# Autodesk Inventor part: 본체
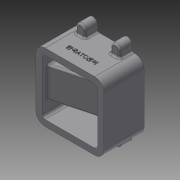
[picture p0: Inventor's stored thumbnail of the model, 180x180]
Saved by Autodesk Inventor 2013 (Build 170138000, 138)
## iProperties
Created: 2018-01
Part Number: 본체
Material: 일반
Document SubType Name: Modeling
Designer: Administrator
Density: 1 g/cm^3
Author: Administrator
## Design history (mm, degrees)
sketch "스케치1"
  geometry: L1 (55, -55)-(-55, -55); L2 (-55, -55)-(-55, 55); L3 (-55, 55)-(55, 55); L4 (55, 55)-(55, -55); 3 further points
  constraints: 8 end point, 2 midpoint, 2 parallel, 1 horizontal, 1 horizontal alignment, 1 perpendicular, 1 vertical alignment
  dimensions: "d0" = 110 distance of L1.start L1.end; "d2" = 110 distance of L3.end L1.start
extrude "돌출1" new body sketch "스케치1" distance "d3" = 65; taper "d4" = 0 deg
fillet "모깎기1" dims "d5" = 15
sketch "스케치3"
  geometry: L1 (40, 55)-(-40, 55) reference; L2 (-55, 40)-(-55, -40) reference; L3 (-40, -55)-(40, -55) reference; L4 (55, -40)-(55, 40) reference; L5 (-40, 45)-(40, 45); L6 (45, 40)-(45, -40); L7 (40, -45)-(-40, -45); L8 (-45, -40)-(-45, 40); A1 r 15 centre (40, 40) between (55, 40) and (40, 55) reference; A2 r 15 centre (-40, 40) between (-40, 55) and (-55, 40) reference; A3 r 15 centre (-40, -40) between (-55, -40) and (-40, -55) reference; A4 r 15 centre (40, -40) between (40, -55) and (55, -40) reference; A5 r 5 centre (40, 40) between (45, 40) and (40, 45); A6 r 5 centre (40, -40) between (40, -45) and (45, -40); A7 r 5 centre (-40, -40) between (-45, -40) and (-40, -45); A8 r 5 centre (-40, 40) between (-40, 45) and (-45, 40); 1 further point
  constraints: 8 end point, 8 point on circle, 4 centre point, 7 other
  dimensions: "d6" = 10 distance between parallel lines of L5 L1
extrude "돌출2" cut sketch "스케치3" stored distance "d7" = 65; taper "d8" = 0 deg
sketch "스케치10"
  geometry: L1 (-45, 65)-(35, 65); L2 (-45, 65)-(-45, 8.564); L3 (-45, 8.564)-(35, 30); L4 (35, 30)-(35, 65); L5 (-55, 0)-(-55, 65) reference; L6 (40, 0)-(-40, 0) reference; L7 (55, 65)-(55, 0) reference; 1 further point
  constraints: 8 end point, 1 horizontal, 1 parallel, 1 perpendicular
  dimensions: "d54" = 65 distance from line of L1 point (0, 0); "d55" = 10 distance between parallel lines of L2 L5; "d56" = 105 deg angle of L3 L5; "d57" = 30 distance from line of L3.end L6; "d58" = 20 distance between parallel lines of L4 L7
extrude "돌출4" join sketch "스케치10" stored distance "d59" = 50; taper "d60" = 0 deg
sketch "스케치11"
  geometry: L1 (-55, 40)-(-55, -40) reference; L2 (55, -40)-(55, 40) reference; L3 (-55, 7.5)-(-36, 7.5); L4 (-36, 7.5)-(-36, 16); L5 (-36, 16)-(-22, 16); L6 (-22, 16)-(-22, 20); L7 (-22, 20)-(25, 20); L8 (25, 20)-(25, 15); L9 (25, 15)-(30, 15); L10 (30, 15)-(30, 0); L11 (30, 0)-(-55, 0); L12 (-55, 7.5)-(-55, 0); 3 further points
  constraints: 20 end point, 6 parallel, 3 midpoint, 3 perpendicular, 2 collinear, 1 horizontal alignment
  dimensions: "d61" = 15 diameter of L3 L11; "d63" = 32 diameter of L5 L11; "d64" = 40 diameter of L7 L11; "d65" = 30 diameter of L9 L11; "d66" = 19 distance of L3.start L3.end; "d67" = 14 distance of L4.end L5.end; "d68" = 5 distance of L8.end L9.end; "d69" = 47 distance of L6.end L7.end
revolve "회전1" sketch "스케치11" stored, may be unused: angle "d70" = 90 deg
sketch "스케치15"
  geometry: L1 (20, -15)-(-17, -15); L2 (-17, -15)-(-17, 15); L3 (-22, 16)-(-22, 20) reference; L4 (-45, 25)-(-45, 40) reference; L5 (-17, 15)-(20, 15); L6 (20, 15)-(20, -15); 3 further points
  constraints: 8 end point, 2 horizontal alignment, 2 midpoint, 2 perpendicular
  dimensions: "d86" = 37 distance of L2.end L5.end; "d88" = 30 distance of L5.end L1.start; "d89" = 5 distance between parallel lines of L2 L3
extrude "돌출6" cut sketch "스케치15" distance "d84" = 30; taper "d85" = 0 deg
sketch "스케치13"
  geometry: L1 (-17, 45)-(-17, 39.243); L2 (-17, 39.243)-(-55, 29.061); L3 (-55, 11.061)-(20, 31.157); L4 (20, 31.157)-(20, 45); L5 (-55, 0)-(-55, 65) reference; L6 (35, 30)-(-45, 8.564) reference; L7 (-22, 65)-(-22, 45) reference; L8 (25, 65)-(25, 45) reference; L9 (-17, 45)-(20, 45); L10 (25, 45)-(-22, 45) reference; L11 (-55, 29.061)-(-55, 11.061); 1 further point
  constraints: 12 end point, 3 parallel, 2 perpendicular, 2 point on line, 1 collinear, 1 vertical
  dimensions: "d75" = 5 distance between parallel lines of L3 L6; "d76" = 37 distance between parallel lines of L4 L1; "d77" = 5 distance between parallel lines of L1 L7; "d127" = 18 distance of L3.start L2.end
extrude "돌출5" cut sketch "스케치13" stored distance "d79" = 30; taper "d80" = 0 deg
sketch "스케치17"
  geometry: L1 (40, 55)-(-40, 55) reference; L2 (-55, 40)-(-55, 7.5) reference; L3 (-45, 25)-(-45, 40) reference; L4 (-35.5, 55)-(-35.5, 65); L5 (-20.5, 65)-(-20.5, 55); L6 (-35.5, 55)-(-20.5, 55); L7 (20.5, 55)-(20.5, 65); L8 (35.5, 65)-(35.5, 55); L9 (20.5, 55)-(35.5, 55); A1 r 7.5 centre (-28, 65) between (-20.5, 65) and (-35.5, 65); A2 r 7.5 centre (28, 65) between (35.5, 65) and (20.5, 65); 1 further point
  constraints: 12 end point, 4 point on circle, 4 point on line, 4 tangent, 2 centre point, 2 collinear, 2 parallel, 2 perpendicular
  dimensions: "d90" = 27 distance from line of A1.centre L2; "d91" = 7.5 radius of A1; "d92" = 10 distance from line of A1.centre L1; "d93" = 7.5 radius of A2; "d94" = 10 distance from line of L1 A2.centre; "d95" = 56 distance of A2.centre A1.centre
extrude "돌출7" join sketch "스케치17" distance "d96" = 20; taper "d97" = 0 deg
sketch "스케치18"
  geometry: A1 r 7.5 centre (28, 65) between (35.5, 65) and (20.5, 65) reference; A2 r 7.5 centre (-28, 65) between (-20.5, 65) and (-35.5, 65) reference; 3 further points
  constraints: 2 coincident
hole "구멍1" sketch "스케치18" at (-28, 65), (28, 65) diameter "d98" = 3.242; stored, may be unused: countersink angle "d102" = 90 deg, drill point angle "d104" = 118 deg; dims "d99" = 9, "d100" = 4, "d101" = 2, "d103" = 11
fillet "모깎기2" dims "d105" = 3
fillet "모깎기3" dims "d106" = 3
fillet "모깎기4" dims "d107" = 3
fillet "모깎기7" dims "d110" = 1
chamfer "모따기1" distance "d111" = 1; stored, may be unused: second distance "d112" = 2, angle "d113" = 45 deg
fillet "모깎기8" dims "d114" = 3
fillet "모깎기9" dims "d115" = 3
fillet "모깎기12" dims "d118" = 3
fillet "모깎기13" dims "d119" = 3
fillet "모깎기14" dims "d120" = 3
fillet "모깎기15" dims "d121" = 3
fillet "모깎기16" dims "d122" = 3
sketch "스케치19"
  geometry: L1 (80, 0)-(0, 0) reference; L2 (-15, 65)-(-15, 0) reference; 2 further points
  constraints: 1 other
  dimensions: "d123" = 20 distance from line of point (40, 20) L1; "d124" = 55 distance from line of point (40, 20) L2
feature "엠보싱1" sketch "스케치19" dims "d0" = 110, "d2" = 110, "d125" = 0.5, "d126" = 0
node "솔리드1"
mirror "대칭1"
